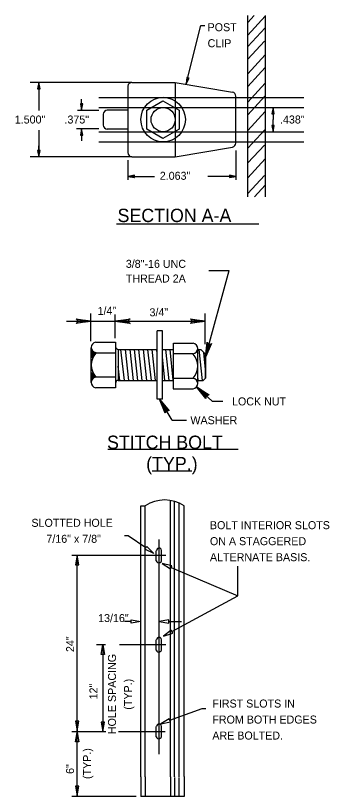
# Model space of a CAD drawing. Extents: x 150.3 to 157.3, y 91.3 to 101.4.
# Drawn here: x 154.61 to 156.97, y 95.57 to 101.42 of the extents above; entities that cross this region are included whole.
import ezdxf

# ---------------------------------------------------------------- set-up
doc = ezdxf.new("R2010")
doc.units = 0
for name, color, linetype in [('DETL-DIMS', 7, 'Continuous'), ('DETL-LINE', 7, 'Continuous'), ('DETL-NOTE', 7, 'Continuous'), ('DETL-PATT', 7, 'Continuous'), ('DETL-TITL', 7, 'Continuous')]:
    doc.layers.add(name, color=color, linetype=linetype)

msp = doc.modelspace()

# ---------------------------------------------------------------- linework, layer by layer
at = {"layer": 'DETL-DIMS'}
for p, q in [((155.8942, 100.9121), (156.0042, 101.3496)), ((156.0042, 101.3496), (156.0325, 101.3496)), ((155.485, 100.9229), (154.7217, 100.9229)), ((154.7868, 100.9229), (154.7868, 100.8338)), ((154.7868, 100.9229), (154.7868, 100.7118)), ((155.1081, 100.7154), (155.1081, 100.7979)), ((156.5459, 100.7346), (156.5459, 100.6454)), ((155.2364, 100.7138), (155.0774, 100.7138)), ((156.5459, 100.5529), (156.5459, 100.6454)), ((154.7868, 100.5642), (154.7868, 100.3661)), ((155.2382, 100.5754), (155.0709, 100.5754)), ((155.1081, 100.5754), (155.1081, 100.4863)), ((154.7868, 100.3661), (154.7868, 100.4486)), ((156.265, 100.4129), (156.265, 100.1921)), ((155.4859, 100.3661), (154.7226, 100.3661)), ((155.4559, 100.3413), (155.4559, 100.1921)), ((155.4575, 100.2188), (155.6551, 100.2188)), ((156.265, 100.2188), (156.0554, 100.2188)), ((156.0376, 98.862), (156.2166, 99.5124)), ((156.0626, 99.5124), (156.2166, 99.5124)), ((155.1777, 98.9833), (155.1777, 99.1892)), ((155.3609, 99.0049), (155.3609, 99.1822)), ((156.0352, 98.96), (156.0352, 99.1892)), ((154.9957, 99.1321), (155.1789, 99.1321)), ((155.1777, 99.1321), (155.3609, 99.1321)), ((155.3609, 99.1321), (156.0364, 99.1321)), ((156.0895, 98.5336), (155.9711, 98.6403)), ((155.7891, 98.3895), (155.6934, 98.5476)), ((156.0895, 98.5336), (156.1682, 98.5336)), ((155.7891, 98.3895), (155.8946, 98.3895)), ((155.689, 97.496), (155.689, 95.8844)), ((155.034, 97.3777), (155.2365, 97.3777)), ((155.0756, 96.0544), (155.0756, 97.3777)), ((155.2298, 97.3777), (155.7412, 97.3777)), ((155.7806, 97.286), (156.2806, 97.0719)), ((156.2806, 97.0719), (156.2806, 97.2956)), ((155.7856, 96.8044), (156.2806, 97.0719)), ((155.4798, 96.8802), (155.4306, 96.8802)), ((155.764, 96.8802), (155.8573, 96.8802)), ((155.2198, 96.7069), (155.2881, 96.7069)), ((155.2673, 96.7069), (155.2673, 96.0544)), ((155.393, 96.7069), (155.7412, 96.7069)), ((155.7706, 96.1394), (156.0125, 96.2281)), ((156.0125, 96.2281), (156.0408, 96.2281)), ((155.034, 96.0544), (155.2331, 96.0544)), ((155.0756, 95.5685), (155.0756, 96.0544)), ((155.2165, 96.0544), (155.2898, 96.0544)), ((155.3852, 96.0544), (155.7367, 96.0544)), ((155.2873, 95.5685), (155.034, 95.5685)), ((155.519, 95.5685), (155.259, 95.5685))]:
    msp.add_line(p, q, dxfattribs=at)
for points in [[(155.8975, 100.9604), (155.8942, 100.9121), (155.915, 100.9563), (155.8975, 100.9604)], [(155.8984, 100.9588), (155.8959, 100.9188), (155.9134, 100.9554), (155.8984, 100.9588)], [(155.8992, 100.9571), (155.8975, 100.9238), (155.9117, 100.9546), (155.8992, 100.9571)], [(155.9009, 100.9563), (155.8984, 100.9304), (155.91, 100.9529), (155.9009, 100.9563)], [(155.9017, 100.9546), (155.9009, 100.9363), (155.9084, 100.9529), (155.9017, 100.9546)], [(155.9025, 100.9529), (155.9025, 100.9421), (155.9067, 100.9521), (155.9025, 100.9529)], [(154.796, 100.8763), (154.7868, 100.9229), (154.7776, 100.8763), (154.796, 100.8763)], [(154.7943, 100.8771), (154.7868, 100.9171), (154.7793, 100.8771), (154.7943, 100.8771)], [(154.7926, 100.8779), (154.7868, 100.9104), (154.7801, 100.8779), (154.7926, 100.8779)], [(154.7918, 100.8796), (154.7868, 100.9046), (154.7818, 100.8796), (154.7918, 100.8796)], [(154.7901, 100.8804), (154.7868, 100.8988), (154.7835, 100.8804), (154.7901, 100.8804)], [(155.9034, 100.9513), (155.9034, 100.9488), (155.905, 100.9513), (155.9034, 100.9513)], [(154.7885, 100.8813), (154.7868, 100.8929), (154.7843, 100.8813), (154.7885, 100.8813)], [(154.7876, 100.8829), (154.7868, 100.8863), (154.786, 100.8829), (154.7876, 100.8829)], [(155.0989, 100.7629), (155.1081, 100.7154), (155.1173, 100.7629), (155.0989, 100.7629)], [(155.1006, 100.7613), (155.1081, 100.7221), (155.1156, 100.7613), (155.1006, 100.7613)], [(155.1014, 100.7613), (155.1081, 100.7279), (155.1139, 100.7613), (155.1014, 100.7613)], [(155.1031, 100.7596), (155.1081, 100.7346), (155.1131, 100.7596), (155.1031, 100.7596)], [(155.1048, 100.7579), (155.1081, 100.7404), (155.1114, 100.7579), (155.1048, 100.7579)], [(155.1056, 100.7571), (155.1081, 100.7463), (155.1098, 100.7571), (155.1056, 100.7571)], [(155.1073, 100.7563), (155.1081, 100.7529), (155.1089, 100.7563), (155.1073, 100.7563)], [(156.5551, 100.6879), (156.5459, 100.7346), (156.5368, 100.6879), (156.5551, 100.6879)], [(156.5534, 100.6888), (156.5459, 100.7288), (156.5384, 100.6888), (156.5534, 100.6888)], [(156.5518, 100.6896), (156.5459, 100.7221), (156.5393, 100.6896), (156.5518, 100.6896)], [(156.5509, 100.6913), (156.5459, 100.7163), (156.5409, 100.6913), (156.5509, 100.6913)], [(156.5493, 100.6921), (156.5459, 100.7104), (156.5426, 100.6921), (156.5493, 100.6921)], [(156.5476, 100.6929), (156.5459, 100.7046), (156.5434, 100.6929), (156.5476, 100.6929)], [(156.5468, 100.6946), (156.5459, 100.6979), (156.5451, 100.6946), (156.5468, 100.6946)], [(155.1173, 100.5288), (155.1081, 100.5754), (155.0989, 100.5288), (155.1173, 100.5288)], [(155.1156, 100.5296), (155.1081, 100.5696), (155.1006, 100.5296), (155.1156, 100.5296)], [(155.1139, 100.5304), (155.1081, 100.5629), (155.1014, 100.5304), (155.1139, 100.5304)], [(155.1131, 100.5321), (155.1081, 100.5571), (155.1031, 100.5321), (155.1131, 100.5321)], [(155.1114, 100.5329), (155.1081, 100.5513), (155.1048, 100.5329), (155.1114, 100.5329)], [(155.1098, 100.5338), (155.1081, 100.5454), (155.1056, 100.5338), (155.1098, 100.5338)], [(156.5368, 100.6004), (156.5459, 100.5529), (156.5551, 100.6004), (156.5368, 100.6004)], [(156.5384, 100.5988), (156.5459, 100.5596), (156.5534, 100.5988), (156.5384, 100.5988)], [(156.5393, 100.5988), (156.5459, 100.5654), (156.5518, 100.5988), (156.5393, 100.5988)], [(156.5409, 100.5971), (156.5459, 100.5721), (156.5509, 100.5971), (156.5409, 100.5971)], [(156.5426, 100.5954), (156.5459, 100.5779), (156.5493, 100.5954), (156.5426, 100.5954)], [(156.5434, 100.5946), (156.5459, 100.5838), (156.5476, 100.5946), (156.5434, 100.5946)], [(156.5451, 100.5938), (156.5459, 100.5904), (156.5468, 100.5938), (156.5451, 100.5938)], [(155.1089, 100.5354), (155.1081, 100.5388), (155.1073, 100.5354), (155.1089, 100.5354)], [(154.7776, 100.4136), (154.7868, 100.3661), (154.796, 100.4136), (154.7776, 100.4136)], [(154.7793, 100.4119), (154.7868, 100.3728), (154.7943, 100.4119), (154.7793, 100.4119)], [(154.7801, 100.4119), (154.7868, 100.3786), (154.7926, 100.4119), (154.7801, 100.4119)], [(154.7818, 100.4103), (154.7868, 100.3853), (154.7918, 100.4103), (154.7818, 100.4103)], [(154.7835, 100.4086), (154.7868, 100.3911), (154.7901, 100.4086), (154.7835, 100.4086)], [(154.7843, 100.4078), (154.7868, 100.3969), (154.7885, 100.4078), (154.7843, 100.4078)], [(154.786, 100.4069), (154.7868, 100.4036), (154.7876, 100.4069), (154.786, 100.4069)], [(155.505, 100.2279), (155.4575, 100.2188), (155.505, 100.2096), (155.505, 100.2279)], [(155.5034, 100.2263), (155.4642, 100.2188), (155.5034, 100.2113), (155.5034, 100.2263)], [(155.5025, 100.2246), (155.47, 100.2188), (155.5025, 100.2121), (155.5025, 100.2246)], [(155.5017, 100.2238), (155.4767, 100.2188), (155.5017, 100.2138), (155.5017, 100.2238)], [(155.5, 100.2221), (155.4817, 100.2188), (155.5, 100.2154), (155.5, 100.2221)], [(155.4992, 100.2204), (155.4884, 100.2188), (155.4992, 100.2163), (155.4992, 100.2204)], [(155.4984, 100.2196), (155.4942, 100.2188), (155.4984, 100.2179), (155.4984, 100.2196)], [(156.2184, 100.2096), (156.265, 100.2188), (156.2184, 100.2279), (156.2184, 100.2096)], [(156.2192, 100.2113), (156.2592, 100.2188), (156.2192, 100.2263), (156.2192, 100.2113)], [(156.22, 100.2121), (156.2525, 100.2188), (156.22, 100.2246), (156.22, 100.2121)], [(156.2217, 100.2138), (156.2467, 100.2188), (156.2217, 100.2238), (156.2217, 100.2138)], [(156.2234, 100.2154), (156.2409, 100.2188), (156.2234, 100.2221), (156.2234, 100.2154)], [(156.2234, 100.2163), (156.235, 100.2188), (156.2234, 100.2204), (156.2234, 100.2163)], [(156.225, 100.2179), (156.2284, 100.2188), (156.225, 100.2196), (156.225, 100.2179)], [(155.0727, 99.1455), (155.0768, 99.1379), (155.1789, 99.1321), (155.0727, 99.1455), (155.0675, 99.1502), (155.1789, 99.1321), (155.0768, 99.1268), (155.0733, 99.1192), (155.1789, 99.1321), (155.0675, 99.1146), (155.0733, 99.1192)], [(155.4671, 99.1187), (155.463, 99.1262), (155.3609, 99.1321), (155.4671, 99.1187), (155.4723, 99.114), (155.3609, 99.1321), (155.463, 99.1373), (155.4665, 99.1449), (155.3609, 99.1321), (155.4723, 99.1496), (155.4665, 99.1449)], [(155.9302, 99.1455), (155.9343, 99.1379), (156.0364, 99.1321), (155.9302, 99.1455), (155.925, 99.1502), (156.0364, 99.1321), (155.9343, 99.1268), (155.9308, 99.1192), (156.0364, 99.1321), (155.925, 99.1146), (155.9308, 99.1192)], [(156.0784, 98.9606), (156.0702, 98.9588), (156.0376, 98.862), (156.0784, 98.9606), (156.0842, 98.9647), (156.0376, 98.862), (156.0597, 98.9617), (156.0533, 98.967), (156.0376, 98.862), (156.0498, 98.974), (156.0533, 98.967)], [(156.0411, 98.5592), (156.0428, 98.568), (155.9711, 98.6403), (156.0411, 98.5592), (156.0416, 98.5522), (155.9711, 98.6403), (156.0504, 98.5756), (156.058, 98.5791), (155.9711, 98.6403), (156.0656, 98.5791), (156.058, 98.5791)], [(155.7371, 98.4502), (155.7412, 98.4572), (155.6934, 98.5476), (155.7371, 98.4502), (155.736, 98.4432), (155.6934, 98.5476), (155.7506, 98.463), (155.7587, 98.4636), (155.6934, 98.5476), (155.7663, 98.4612), (155.7587, 98.4636)], [(155.5898, 97.4319), (155.459, 97.5227), (155.4306, 97.5227)]]:
    msp.add_lwpolyline(points, dxfattribs=at)
for points in [[(155.5831, 97.4227), (155.5973, 97.4427), (155.6498, 97.3902)], [(155.0631, 97.3052), (155.0881, 97.3052), (155.0756, 97.3777)], [(155.7765, 97.2744), (155.7856, 97.2969), (155.714, 97.3144)], [(155.4798, 96.8685), (155.4798, 96.8919), (155.5523, 96.8802)], [(155.764, 96.8685), (155.764, 96.8919), (155.6898, 96.8802)], [(155.7923, 96.7935), (155.7806, 96.8144), (155.7223, 96.7694)], [(155.2798, 96.6335), (155.2556, 96.6335), (155.2673, 96.7069)], [(155.0881, 96.1319), (155.0631, 96.1319), (155.0756, 96.0602)], [(155.2798, 96.126), (155.2556, 96.126), (155.2673, 96.0544)], [(155.7748, 96.1269), (155.7665, 96.1502), (155.7023, 96.1135)], [(155.0881, 95.9769), (155.0631, 95.9769), (155.0756, 96.0485)], [(155.0881, 95.6452), (155.0631, 95.6452), (155.0756, 95.5735)]]:
    msp.add_lwpolyline(points, close=True, dxfattribs=at)
at = {"layer": 'DETL-LINE'}
for p, q in [((156.3542, 101.4242), (156.3542, 100.0654)), ((156.4867, 101.4242), (156.4867, 100.0654)), ((155.455, 100.8954), (155.455, 100.3963)), ((155.485, 100.9229), (155.81, 100.9229)), ((155.81, 100.9229), (156.24, 100.8504)), ((155.81, 100.9229), (155.81, 100.3654)), ((155.2382, 100.8096), (155.455, 100.8096)), ((155.455, 100.8096), (156.7779, 100.8096)), ((155.5984, 100.7146), (155.7192, 100.7846)), ((155.7192, 100.7846), (155.8417, 100.7146)), ((156.2659, 100.4679), (156.2659, 100.8204)), ((155.2382, 100.7346), (155.455, 100.7346)), ((155.455, 100.7346), (156.7779, 100.7346)), ((155.271, 100.6846), (155.271, 100.6038)), ((155.455, 100.7146), (155.301, 100.7146)), ((155.5984, 100.5738), (155.5984, 100.7146)), ((155.8417, 100.7146), (155.8417, 100.5738)), ((155.2382, 100.5529), (155.455, 100.5529)), ((155.455, 100.5738), (155.301, 100.5738)), ((155.455, 100.5529), (156.7779, 100.5529)), ((155.7192, 100.5029), (155.5984, 100.5738)), ((155.8417, 100.5738), (155.7192, 100.5029)), ((155.2382, 100.4771), (155.455, 100.4771)), ((155.455, 100.4771), (156.7779, 100.4771)), ((155.81, 100.3654), (156.24, 100.4379)), ((155.485, 100.3654), (155.81, 100.3654)), ((155.7156, 99.0609), (155.6759, 99.0609)), ((155.6759, 98.547), (155.6759, 99.0609)), ((155.7156, 98.547), (155.7156, 99.0609)), ((155.2151, 98.9763), (155.3626, 98.9763)), ((155.3626, 98.9746), (155.3626, 98.6333)), ((155.7961, 98.9664), (155.7961, 98.6252)), ((155.7972, 98.967), (155.9466, 98.967)), ((155.1801, 98.6736), (155.1801, 98.9337)), ((155.3831, 98.9203), (155.3831, 98.6887)), ((155.3848, 98.9203), (155.6759, 98.9203)), ((155.4295, 98.6887), (155.4038, 98.9203)), ((155.4632, 98.6887), (155.4376, 98.9203)), ((155.4971, 98.6887), (155.4721, 98.9203)), ((155.5309, 98.6887), (155.5052, 98.9203)), ((155.563, 98.6887), (155.5373, 98.9203)), ((155.5974, 98.6887), (155.5723, 98.9203)), ((155.6318, 98.6887), (155.6067, 98.9203)), ((155.6627, 98.6887), (155.6371, 98.9203)), ((155.6765, 98.8871), (155.6731, 98.9203)), ((155.7156, 98.9203), (155.7961, 98.9203)), ((155.7646, 98.6887), (155.7407, 98.9203)), ((155.7961, 98.6911), (155.7724, 98.9203)), ((155.9798, 98.6631), (155.9798, 98.9232)), ((155.9798, 98.9203), (156.0041, 98.9203)), ((156.0148, 98.6887), (155.9909, 98.9203)), ((156.0041, 98.9203), (156.0376, 98.8853)), ((155.1801, 98.8952), (155.3626, 98.8952)), ((155.7338, 98.6887), (155.7156, 98.8643)), ((155.946, 98.8871), (155.7978, 98.8871)), ((156.0376, 98.8853), (156.0241, 98.8993)), ((156.0381, 98.7692), (156.0247, 98.8987)), ((156.0376, 98.7062), (156.0376, 98.8853)), ((156.0376, 98.8853), (156.0376, 98.7062)), ((155.3956, 98.6887), (155.3831, 98.7943)), ((155.3393, 98.7127), (155.1801, 98.7127)), ((155.3626, 98.7127), (155.3393, 98.7127)), ((155.3836, 98.6887), (155.6759, 98.6887)), ((155.7156, 98.6887), (155.7961, 98.6887)), ((155.7961, 98.7045), (155.9489, 98.7045)), ((155.9798, 98.6887), (156.0209, 98.6887)), ((155.984, 98.6887), (155.9804, 98.7232)), ((156.0201, 98.6887), (156.0376, 98.7062)), ((156.0376, 98.7062), (156.0209, 98.6887)), ((155.3626, 98.6333), (155.2139, 98.6333)), ((155.7961, 98.6252), (155.9466, 98.6252)), ((155.7156, 98.547), (155.6759, 98.547)), ((155.5523, 97.4652), (155.5523, 97.7477)), ((155.5523, 97.7477), (155.5848, 97.7477)), ((155.5848, 97.4652), (155.5848, 97.7477)), ((155.7765, 97.4652), (155.7765, 97.7877)), ((155.8056, 97.4652), (155.8056, 97.7794)), ((155.8415, 97.4652), (155.8415, 97.7669)), ((155.8773, 97.4652), (155.8773, 97.7477)), ((155.5523, 95.7144), (155.5523, 97.4652)), ((155.5848, 95.7152), (155.5848, 97.4652)), ((155.7765, 95.7152), (155.7765, 97.4652)), ((155.8056, 95.7144), (155.8056, 97.4652)), ((155.8415, 95.7177), (155.8415, 97.4652)), ((155.8773, 95.7177), (155.8773, 97.4652)), ((155.669, 97.3352), (155.669, 97.411)), ((155.7081, 97.341), (155.7081, 97.411)), ((155.669, 96.6644), (155.669, 96.7419)), ((155.7081, 96.6727), (155.7081, 96.7419)), ((155.669, 96.0152), (155.669, 96.0919)), ((155.7081, 96.0227), (155.7081, 96.0919)), ((155.5523, 95.7144), (155.5523, 95.5685)), ((155.5848, 95.7152), (155.5848, 95.5685)), ((155.7765, 95.7152), (155.7765, 95.5685)), ((155.8056, 95.7144), (155.8056, 95.7135)), ((155.8056, 95.7069), (155.8056, 95.5685)), ((155.8415, 95.7135), (155.8415, 95.7177)), ((155.8415, 95.5685), (155.8415, 95.7069)), ((155.8773, 95.7177), (155.8773, 95.5685)), ((155.8773, 95.5685), (155.5523, 95.5685))]:
    msp.add_line(p, q, dxfattribs=at)
for points in [[(155.1882, 98.8999), (155.1871, 98.8667), (155.1981, 98.8842), (155.2016, 98.8923), (155.1859, 98.9017), (155.1906, 98.8888), (155.1859, 98.8579), (155.197, 98.8789), (155.2016, 98.89), (155.1841, 98.9069), (155.1859, 98.8993)], [(155.1888, 98.7068), (155.1876, 98.7401), (155.1987, 98.7226), (155.2022, 98.7144), (155.1865, 98.7051), (155.1911, 98.7179), (155.1865, 98.7488), (155.1976, 98.7278), (155.2022, 98.7167), (155.1847, 98.6998), (155.1865, 98.7074)]]:
    msp.add_lwpolyline(points, dxfattribs=at)
for radius in [0.167, 0.0907]:
    msp.add_circle((155.7204, 100.6444), radius, dxfattribs=at)
for centre, radius, start, end in [((155.4859, 100.8925), 0.0304, 90, 174.27083), ((156.2361, 100.8205), 0.0304, 0, 80.46065), ((155.301, 100.6846), 0.03, 90, 180), ((155.301, 100.6038), 0.03, 180, 270), ((156.2361, 100.4685), 0.0304, 279.53935, 0), ((155.4859, 100.3965), 0.0304, 180, 270), ((155.3848, 98.9413), 0.021, 180, 270), ((155.3836, 98.6677), 0.021, 90, 180), ((155.7319, 97.5263), 0.2653, 56.51178, 123.48822), ((155.6892, 97.4121), 0.0191, 2.16432, 183.33875), ((155.6883, 97.3403), 0.0201, 198.30154, 5.59027), ((155.6892, 96.7427), 0.0191, 2.16432, 183.33875), ((155.6883, 96.6709), 0.0201, 198.30154, 5.59027), ((155.6892, 96.0927), 0.0191, 2.16432, 183.33875), ((155.6883, 96.0208), 0.0201, 198.30154, 5.59027)]:
    msp.add_arc(centre, radius, start, end, dxfattribs=at)
for centre, major_axis, ratio, start_param, end_param in [((155.2259, 98.936), (-0.0457, 0), 0.888639, 4.948347, 7.618023), ((155.9345, 98.9278), (0.0457, 0), 0.888639, 4.948347, 7.618023), ((155.3444, 98.8038), (-0.1642, 0), 0.88864, 5.618065, 6.948305), ((155.816, 98.7956), (0.1642, 0), 0.88864, 5.618065, 6.948305), ((155.2274, 98.6732), (-0.0472, 0), 0.888639, 4.973303, 7.593068), ((155.9331, 98.6651), (0.0472, 0), 0.88864, 4.973303, 7.593068)]:
    msp.add_ellipse(centre, major_axis=major_axis, ratio=ratio, start_param=start_param, end_param=end_param, dxfattribs=at)
at = {"layer": 'DETL-PATT'}
for p, q in [((156.3567, 101.3738), (156.4037, 101.4242)), ((156.3567, 101.2788), (156.4875, 101.4204)), ((156.3567, 101.1921), (156.4875, 101.3338)), ((156.3567, 101.0979), (156.4809, 101.2321)), ((156.3567, 100.9879), (156.4875, 101.1296)), ((156.3567, 100.8938), (156.4875, 101.0354)), ((156.3567, 100.7754), (156.4875, 100.9171)), ((156.3567, 100.6813), (156.4875, 100.8229)), ((156.3567, 100.5629), (156.4875, 100.7046)), ((156.3567, 100.4296), (156.4875, 100.5713)), ((156.3567, 100.3196), (156.4809, 100.4529)), ((156.3567, 100.2088), (156.4875, 100.3504)), ((156.3567, 100.0904), (156.4809, 100.2246)), ((156.4059, 100.0654), (156.4875, 100.1538))]:
    msp.add_line(p, q, dxfattribs=at)
at = {"layer": 'DETL-TITL'}
for p, q in [((155.3697, 99.8624), (156.4378, 99.8624)), ((155.3048, 98.1725), (156.2836, 98.1725)), ((155.6381, 98.0094), (155.9368, 98.0094))]:
    msp.add_line(p, q, dxfattribs=at)

# ---------------------------------------------------------------- texts
at = {"layer": 'DETL-NOTE'}
for s, p in [('POST', (156.0542, 101.3071)), ('CLIP', (156.0542, 101.1871)), ('1.500"', (154.6066, 100.615)), ('.375"', (154.9797, 100.615)), ('.438"', (156.5978, 100.615)), ('2.063"', (155.6951, 100.1929)), ('3/8"-16 UNC', (155.4401, 99.5326)), ('THREAD 2A', (155.4401, 99.4226)), ('LOCK NUT', (156.2375, 98.5008)), (' WASHER', (155.9028, 98.3598)), ('SLOTTED HOLE', (154.7317, 97.5902)), ('BOLT INTERIOR SLOTS ', (156.0718, 97.5726)), ('7/16" x 7/8"', (154.8437, 97.4702)), ('ON A STAGGERED ', (156.0718, 97.4526)), ('ALTERNATE BASIS.', (156.0718, 97.3326)), ('13/16"', (155.2323, 96.876)), ('FIRST SLOTS IN ', (156.0899, 96.2348)), ('FROM BOTH EDGES', (156.0899, 96.1148)), ('ARE BOLTED.', (156.0899, 95.9948))]:
    msp.add_text(s, height=0.06, dxfattribs=at).set_placement(p)
for s, rotation, p in [('1/4"', 1, (155.2288, 99.1793)), ('3/4"', 1, (155.6188, 99.1686)), ('24"', 90, (155.0523, 96.651)), ('HOLE SPACING', 90, (155.3665, 96.0352)), ('(TYP.)', 90, (155.4865, 96.2185)), ('12"', 90, (155.2273, 96.296)), ('(TYP.)', 90, (155.179, 95.6985)), ('6"', 90, (155.0515, 95.7369))]:
    msp.add_text(s, height=0.06, rotation=rotation, dxfattribs=at).set_placement(p)
at = {"layer": 'DETL-TITL'}
for s, p in [('SECTION A-A', (155.378, 99.8757)), ('STITCH BOLT', (155.2993, 98.1741)), ('(TYP.)', (155.593, 98.0141))]:
    msp.add_text(s, height=0.1, dxfattribs=at).set_placement(p)

doc.saveas('drawing.dxf')
